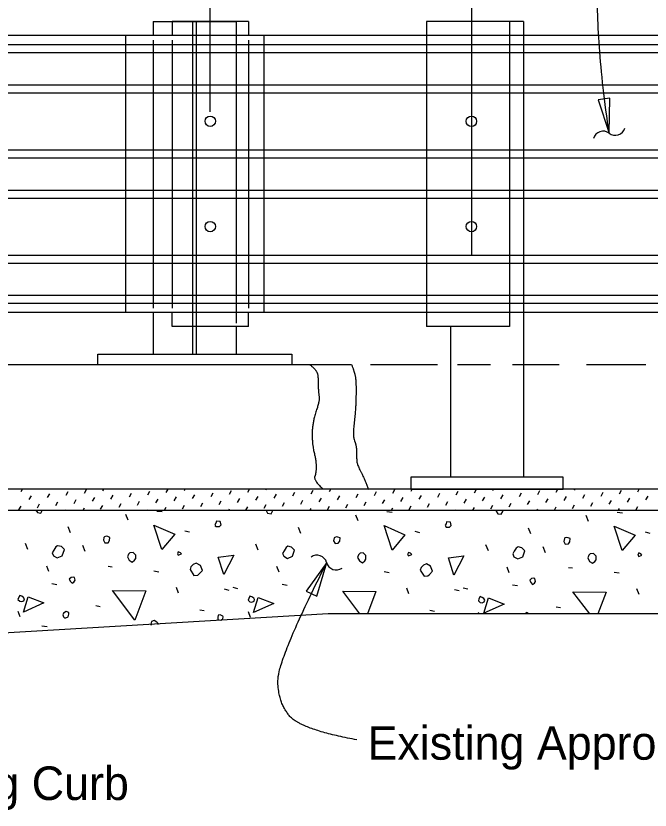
# Model space of a CAD drawing. Extents: x 21652.5 to 21723.2, y 56079.2 to 56117.9.
# Drawn here: x 21666.877 to 21670.692, y 56092.512 to 56097.288 of the extents above; entities that cross this region are included whole.
import ezdxf

# ---------------------------------------------------------------- set-up
doc = ezdxf.new("R2010")
doc.units = 0
for name, color, linetype in [('Dimension', 7, 'Continuous'), ('ExistSuperStruct', 7, 'Continuous'), ('Miscellaneous', 7, 'Continuous'), ('SteelMisc', 7, 'Continuous'), ('SteelMisc_h', 7, 'Continuous'), ('TextStructures', 7, 'Continuous')]:
    doc.layers.add(name, color=color, linetype=linetype)

msp = doc.modelspace()

# ---------------------------------------------------------------- linework, layer by layer
at = {"layer": 'Dimension'}
for points in [[(21670.4443, 56096.5821), (21670.4498, 56096.7932), (21670.3799, 56096.7832)], [(21668.7463, 56094.0005), (21668.6232, 56093.8288), (21668.6866, 56093.7979)]]:
    msp.add_lwpolyline(points, close=True, dxfattribs=at)
for centre, start, end in [((21670.4815, 56096.6294), 232.3142, 344.0414), ((21670.4086, 56096.535), 52.3142, 164.0414), ((21668.6877, 56093.9857), 14.5413, 126.2686), ((21668.8031, 56094.0157), 194.5413, 306.2686)]:
    msp.add_arc(centre, 0.0596, start, end, dxfattribs=at)
for points in [[(21670.4443, 56096.582), (21670.2321, 56098.0664), (21670.6716, 56098.0664)], [(21668.9275, 56092.9348), (21668.5908, 56092.9968), (21668.4527, 56093.1627), (21668.4527, 56093.4184), (21668.7461, 56094.0004)]]:
    msp.add_open_spline(points, degree=2, dxfattribs=at)
at = {"layer": 'ExistSuperStruct'}
for p, q in [((21663.535, 56095.1915), (21668.8956, 56095.1915)), ((21669.0102, 56095.1915), (21669.4133, 56095.1915)), ((21669.5335, 56095.1915), (21669.7306, 56095.1915)), ((21669.8642, 56095.1915), (21670.1448, 56095.1915)), ((21670.3084, 56095.1915), (21670.6659, 56095.1915)), ((21673.8983, 56094.4417), (21663.535, 56094.4417)), ((21663.535, 56094.3166), (21673.8983, 56094.3166)), ((21668.7549, 56093.6915), (21664.5351, 56093.4415)), ((21673.8983, 56093.6916), (21668.7549, 56093.6916))]:
    msp.add_line(p, q, dxfattribs=at)
for points in [[(21668.6455, 56095.1902), (21668.6889, 56095.1567), (21668.6956, 56095.0999), (21668.6956, 56095.0231), (21668.7056, 56094.9797), (21668.6589, 56094.8393), (21668.6589, 56094.709), (21668.6823, 56094.6155), (21668.6831, 56094.5403), (21668.6656, 56094.4952), (21668.7257, 56094.4418)], [(21668.8956, 56095.1915), (21668.9161, 56095.14), (21668.9227, 56095.0832), (21668.9227, 56095.0064), (21668.9207, 56094.9263), (21668.9023, 56094.7576), (21668.9248, 56094.7058), (21668.9265, 56094.6356), (21668.9265, 56094.5955), (21668.9758, 56094.4986), (21668.9983, 56094.4401)]]:
    msp.add_open_spline(points, degree=2, dxfattribs=at)
at = {"layer": 'Miscellaneous'}
for p, q in [((21668.046, 56096.7118), (21668.046, 56100.8638)), ((21669.6168, 56099.3652), (21669.6168, 56095.8462)), ((21668.2751, 56097.2541), (21667.8167, 56097.2541)), ((21667.8167, 56097.2541), (21667.8167, 56097.1708)), ((21668.2751, 56097.2541), (21668.2751, 56097.1708)), ((21669.8459, 56097.2539), (21669.3459, 56097.2539)), ((21669.3459, 56097.2539), (21669.3459, 56095.4208)), ((21669.8459, 56097.2539), (21669.8459, 56095.4208)), ((21667.5355, 56097.1708), (21667.5355, 56095.5041)), ((21667.8167, 56097.1422), (21667.8167, 56095.5303)), ((21668.2751, 56097.1422), (21668.2751, 56095.5303)), ((21668.3688, 56097.1708), (21668.3688, 56095.5041)), ((21667.5355, 56097.1151), (21673.905, 56097.1151)), ((21667.5355, 56097.0669), (21673.905, 56097.0669)), ((21667.5355, 56096.8741), (21673.905, 56096.8741)), ((21667.5355, 56096.8258), (21673.905, 56096.8258)), ((21667.5355, 56096.4819), (21673.905, 56096.4819)), ((21667.5355, 56096.4336), (21673.905, 56096.4336)), ((21667.5355, 56096.2408), (21673.905, 56096.2408)), ((21667.5355, 56096.1927), (21673.905, 56096.1927)), ((21667.5355, 56095.8487), (21673.905, 56095.8487)), ((21667.5355, 56095.8005), (21673.905, 56095.8005)), ((21667.5355, 56095.6077), (21673.905, 56095.6077)), ((21667.5355, 56095.5595), (21673.905, 56095.5595)), ((21667.8167, 56095.4208), (21667.8167, 56095.5041)), ((21668.2751, 56095.4208), (21668.2751, 56095.5041)), ((21668.2751, 56095.4208), (21667.8167, 56095.4208)), ((21669.8459, 56095.4208), (21669.3459, 56095.4208)), ((21666.9082, 56094.4285), (21666.9159, 56094.4417)), ((21667.0189, 56094.4414), (21667.019, 56094.4417)), ((21667.0677, 56094.3926), (21667.0807, 56094.415)), ((21667.1783, 56094.4056), (21667.1913, 56094.428)), ((21667.289, 56094.4185), (21667.3019, 56094.4409)), ((21667.3996, 56094.4315), (21667.4055, 56094.4417)), ((21667.4484, 56094.3827), (21667.4614, 56094.4051)), ((21667.5591, 56094.3956), (21667.572, 56094.418)), ((21667.6697, 56094.4086), (21667.6827, 56094.431)), ((21667.7803, 56094.4216), (21667.792, 56094.4417)), ((21667.891, 56094.4345), (21667.8951, 56094.4417)), ((21667.9398, 56094.3857), (21667.9528, 56094.4081)), ((21668.0504, 56094.3987), (21668.0634, 56094.421)), ((21668.1611, 56094.4116), (21668.174, 56094.434)), ((21668.2717, 56094.4246), (21668.2816, 56094.4417)), ((21668.3823, 56094.4375), (21668.3847, 56094.4417)), ((21668.4312, 56094.3887), (21668.4441, 56094.4111)), ((21668.5418, 56094.4017), (21668.5548, 56094.4241)), ((21668.6524, 56094.4146), (21668.6654, 56094.437)), ((21668.7631, 56094.4276), (21668.7712, 56094.4417)), ((21668.8737, 56094.4406), (21668.8743, 56094.4417)), ((21668.9225, 56094.3917), (21668.9355, 56094.4141)), ((21669.0332, 56094.4047), (21669.0461, 56094.4271)), ((21669.1438, 56094.4177), (21669.1568, 56094.44)), ((21669.2544, 56094.4306), (21669.2608, 56094.4417)), ((21669.3033, 56094.3818), (21669.3162, 56094.4042)), ((21669.4139, 56094.3947), (21669.4269, 56094.4171)), ((21669.5245, 56094.4077), (21669.5375, 56094.4301)), ((21669.6352, 56094.4207), (21669.6473, 56094.4417)), ((21669.7458, 56094.4336), (21669.7505, 56094.4417)), ((21669.7946, 56094.3848), (21669.8076, 56094.4072)), ((21669.9053, 56094.3978), (21669.9182, 56094.4202)), ((21670.0159, 56094.4107), (21670.0289, 56094.4331)), ((21670.1265, 56094.4237), (21670.1369, 56094.4417)), ((21670.2372, 56094.4367), (21670.2401, 56094.4417)), ((21670.286, 56094.3878), (21670.299, 56094.4102)), ((21670.3966, 56094.4008), (21670.4096, 56094.4232)), ((21670.5073, 56094.4137), (21670.5202, 56094.4361)), ((21670.6179, 56094.4267), (21670.6266, 56094.4417)), ((21666.9571, 56094.3796), (21666.97, 56094.402)), ((21667.1165, 56094.3438), (21667.1295, 56094.3662)), ((21667.2272, 56094.3567), (21667.2401, 56094.3791)), ((21667.3378, 56094.3697), (21667.3508, 56094.3921)), ((21667.4973, 56094.3338), (21667.5102, 56094.3562)), ((21667.6079, 56094.3468), (21667.6209, 56094.3692)), ((21667.7185, 56094.3598), (21667.7315, 56094.3822)), ((21667.8292, 56094.3727), (21667.8421, 56094.3951)), ((21667.9886, 56094.3369), (21668.0016, 56094.3592)), ((21668.0993, 56094.3498), (21668.1122, 56094.3722)), ((21668.2099, 56094.3628), (21668.2229, 56094.3852)), ((21668.3205, 56094.3757), (21668.3335, 56094.3981)), ((21668.48, 56094.3399), (21668.493, 56094.3623)), ((21668.5906, 56094.3528), (21668.6036, 56094.3752)), ((21668.7013, 56094.3658), (21668.7142, 56094.3882)), ((21668.8119, 56094.3788), (21668.8249, 56094.4012)), ((21668.9714, 56094.3429), (21668.9843, 56094.3653)), ((21669.082, 56094.3559), (21669.095, 56094.3782)), ((21669.1926, 56094.3688), (21669.2056, 56094.3912)), ((21669.3521, 56094.3329), (21669.3651, 56094.3553)), ((21669.4627, 56094.3459), (21669.4757, 56094.3683)), ((21669.5734, 56094.3589), (21669.5863, 56094.3813)), ((21669.684, 56094.3718), (21669.697, 56094.3942)), ((21669.8435, 56094.336), (21669.8564, 56094.3584)), ((21669.9541, 56094.3489), (21669.9671, 56094.3713)), ((21670.0647, 56094.3619), (21670.0777, 56094.3843)), ((21670.1754, 56094.3749), (21670.1883, 56094.3973)), ((21670.3348, 56094.339), (21670.3478, 56094.3614)), ((21670.4455, 56094.352), (21670.4584, 56094.3743)), ((21670.5561, 56094.3649), (21670.5691, 56094.3873)), ((21670.6667, 56094.3779), (21670.6797, 56094.4003)), ((21666.8953, 56094.3178), (21666.9082, 56094.3402)), ((21667.0059, 56094.3308), (21667.0189, 56094.3532)), ((21667.1779, 56094.3166), (21667.1783, 56094.3173)), ((21667.281, 56094.3166), (21667.289, 56094.3303)), ((21667.3866, 56094.3209), (21667.3996, 56094.3433)), ((21667.6675, 56094.3166), (21667.6697, 56094.3204)), ((21667.7239, 56094.3106), (21667.7557, 56094.3071)), ((21667.7707, 56094.3166), (21667.7803, 56094.3333)), ((21667.878, 56094.3239), (21667.891, 56094.3463)), ((21668.1572, 56094.3166), (21668.1611, 56094.3234)), ((21668.2603, 56094.3166), (21668.2717, 56094.3363)), ((21668.3694, 56094.3269), (21668.3823, 56094.3493)), ((21668.6468, 56094.3166), (21668.6524, 56094.3264)), ((21668.7501, 56094.317), (21668.7631, 56094.3394)), ((21668.8607, 56094.3299), (21668.8737, 56094.3523)), ((21669.1364, 56094.3166), (21669.1438, 56094.3294)), ((21669.2415, 56094.32), (21669.2544, 56094.3424)), ((21669.5229, 56094.3166), (21669.5245, 56094.3195)), ((21669.626, 56094.3166), (21669.6352, 56094.3324)), ((21669.7328, 56094.323), (21669.7458, 56094.3454)), ((21670.0125, 56094.3166), (21670.0159, 56094.3225)), ((21670.1156, 56094.3166), (21670.1265, 56094.3355)), ((21670.2242, 56094.326), (21670.2372, 56094.3484)), ((21670.5021, 56094.3166), (21670.5073, 56094.3255)), ((21670.6052, 56094.3166), (21670.6179, 56094.3385)), ((21667.5513, 56094.2547), (21667.5372, 56094.29)), ((21668.936, 56094.2511), (21668.9218, 56094.2865)), ((21669.1086, 56094.3071), (21669.1404, 56094.3036)), ((21670.3207, 56094.2476), (21670.3065, 56094.283)), ((21670.4933, 56094.3036), (21670.5251, 56094.3)), ((21667.2054, 56094.1798), (21667.1913, 56094.2152)), ((21667.8919, 56094.1922), (21667.9201, 56094.1851)), ((21668.5901, 56094.1763), (21668.576, 56094.2116)), ((21669.2765, 56094.1886), (21669.3048, 56094.1816)), ((21669.9748, 56094.1727), (21669.9607, 56094.2081)), ((21670.6612, 56094.1851), (21670.6895, 56094.178)), ((21666.9491, 56094.079), (21666.935, 56094.1144)), ((21667.2932, 56094.0673), (21667.2791, 56094.1027)), ((21668.3338, 56094.0755), (21668.3197, 56094.1109)), ((21669.7185, 56094.072), (21669.7043, 56094.1073)), ((21670.0626, 56094.0602), (21670.0484, 56094.0956)), ((21667.0746, 56093.9465), (21667.0623, 56093.98)), ((21667.4311, 56093.9789), (21667.4558, 56093.9754)), ((21668.4593, 56093.9429), (21668.4469, 56093.9765)), ((21669.844, 56093.9394), (21669.8316, 56093.973)), ((21667.7069, 56093.9506), (21667.7369, 56093.9453)), ((21669.0915, 56093.9471), (21669.1216, 56093.9418)), ((21670.2004, 56093.9718), (21670.2252, 56093.9683)), ((21670.4762, 56093.9436), (21670.5063, 56093.9382)), ((21667.0934, 56093.8746), (21667.1235, 56093.8693)), ((21667.8554, 56093.8163), (21667.843, 56093.8499)), ((21668.1294, 56093.8428), (21668.1576, 56093.8357)), ((21668.1818, 56093.8528), (21668.21, 56093.8457)), ((21668.4781, 56093.8711), (21668.5082, 56093.8658)), ((21669.24, 56093.8127), (21669.2277, 56093.8463)), ((21669.514, 56093.8393), (21669.5423, 56093.8322)), ((21669.5664, 56093.8492), (21669.5947, 56093.8422)), ((21669.8628, 56093.8675), (21669.8929, 56093.8622)), ((21670.6247, 56093.8092), (21670.6123, 56093.8428)), ((21667.3568, 56093.742), (21667.3834, 56093.7367)), ((21670.1262, 56093.735), (21670.1527, 56093.7297)), ((21666.9032, 56093.6737), (21666.8908, 56093.7073)), ((21667.9826, 56093.7173), (21668.0092, 56093.712)), ((21668.2878, 56093.6702), (21668.2755, 56093.7038)), ((21669.3673, 56093.7137), (21669.3938, 56093.7084)), ((21669.6633, 56093.6915), (21669.6601, 56093.7002)), ((21667.0333, 56093.6201), (21667.0652, 56093.6165))]:
    msp.add_line(p, q, dxfattribs=at)
for points in [[(21666.9975, 56094.3166), (21667.0057, 56094.3018), (21667.0269, 56094.2982), (21667.0357, 56094.3142), (21667.0363, 56094.3166)], [(21668.3803, 56094.3166), (21668.3815, 56094.3142)], [(21668.3815, 56094.3142), (21668.3904, 56094.2982), (21668.4116, 56094.2947), (21668.4204, 56094.3106), (21668.4219, 56094.3166)], [(21669.7632, 56094.3166), (21669.7662, 56094.3106)], [(21669.7662, 56094.3106), (21669.775, 56094.2947), (21669.7963, 56094.2912), (21669.8051, 56094.3071), (21669.8075, 56094.3166)], [(21667.7546, 56094.0797), (21667.7069, 56094.2264), (21667.8324, 56094.1716), (21667.7546, 56094.0797)], [(21668.0792, 56094.2169), (21668.1004, 56094.2169), (21668.1111, 56094.2275), (21668.1058, 56094.247), (21668.0828, 56094.2488), (21668.0792, 56094.2381), (21668.0739, 56094.2293), (21668.0792, 56094.2169), (21668.0757, 56094.2205)], [(21669.1393, 56094.0761), (21669.0915, 56094.2229), (21669.2171, 56094.1681), (21669.1393, 56094.0761)], [(21669.4639, 56094.2134), (21669.4851, 56094.2134), (21669.4957, 56094.224), (21669.4904, 56094.2434), (21669.4674, 56094.2452), (21669.4639, 56094.2346), (21669.4586, 56094.2258), (21669.4639, 56094.2134), (21669.4604, 56094.2169)], [(21670.5239, 56094.0726), (21670.4762, 56094.2193), (21670.6017, 56094.1645), (21670.5239, 56094.0726)], [(21667.4028, 56094.1345), (21667.4116, 56094.1186), (21667.4311, 56094.1203), (21667.4399, 56094.1327), (21667.4417, 56094.1521), (21667.4293, 56094.1575), (21667.4205, 56094.1592), (21667.4099, 56094.1557), (21667.4063, 56094.1521), (21667.4028, 56094.1345)], [(21668.7875, 56094.1309), (21668.7963, 56094.115), (21668.8158, 56094.1168), (21668.8246, 56094.1292), (21668.8264, 56094.1486), (21668.814, 56094.1539), (21668.8052, 56094.1557), (21668.7946, 56094.1521), (21668.791, 56094.1486), (21668.7875, 56094.1309)], [(21670.1722, 56094.1274), (21670.181, 56094.1115), (21670.2004, 56094.1133), (21670.2093, 56094.1256), (21670.2111, 56094.1451), (21670.1987, 56094.1504), (21670.1898, 56094.1521), (21670.1792, 56094.1486), (21670.1757, 56094.1451), (21670.1722, 56094.1274)], [(21667.1029, 56094.0419), (21667.1259, 56094.0295), (21667.1559, 56094.0419), (21667.1683, 56094.079), (21667.1506, 56094.0967), (21667.1277, 56094.102), (21667.1171, 56094.095), (21667.1047, 56094.0755), (21667.0958, 56094.0596), (21667.1029, 56094.0419)], [(21668.4876, 56094.0384), (21668.5106, 56094.026), (21668.5406, 56094.0384), (21668.553, 56094.0755), (21668.5353, 56094.0932), (21668.5123, 56094.0985), (21668.5017, 56094.0914), (21668.4894, 56094.072), (21668.4805, 56094.0561), (21668.4876, 56094.0384)], [(21669.8723, 56094.0349), (21669.8952, 56094.0225), (21669.9253, 56094.0349), (21669.9377, 56094.072), (21669.92, 56094.0897), (21669.897, 56094.095), (21669.8864, 56094.0879), (21669.874, 56094.0684), (21669.8652, 56094.0525), (21669.8723, 56094.0349)], [(21667.5478, 56094.0355), (21667.5584, 56094.0143), (21667.576, 56094.0037), (21667.5902, 56094.0143), (21667.5973, 56094.0249), (21667.5973, 56094.0461), (21667.5814, 56094.062), (21667.5619, 56094.0602), (21667.5531, 56094.0514), (21667.5478, 56094.0355)], [(21667.8536, 56094.0443), (21667.873, 56094.0532), (21667.866, 56094.0602), (21667.8536, 56094.0655), (21667.8483, 56094.0532), (21667.8536, 56094.0443)], [(21668.127, 56093.9288), (21668.0934, 56094.0331), (21668.1871, 56094.0455), (21668.127, 56093.9288)], [(21668.9324, 56094.0319), (21668.943, 56094.0107), (21668.9607, 56094.0001), (21668.9749, 56094.0107), (21668.9819, 56094.0213), (21668.9819, 56094.0425), (21668.966, 56094.0585), (21668.9466, 56094.0567), (21668.9377, 56094.0479), (21668.9324, 56094.0319)], [(21669.2383, 56094.0408), (21669.2577, 56094.0496), (21669.2506, 56094.0567), (21669.2383, 56094.062), (21669.233, 56094.0496), (21669.2383, 56094.0408)], [(21669.5116, 56093.9252), (21669.4781, 56094.0295), (21669.5717, 56094.0419), (21669.5116, 56093.9252)], [(21670.3171, 56094.0284), (21670.3277, 56094.0072), (21670.3454, 56093.9966), (21670.3595, 56094.0072), (21670.3666, 56094.0178), (21670.3666, 56094.039), (21670.3507, 56094.0549), (21670.3313, 56094.0532), (21670.3224, 56094.0443), (21670.3171, 56094.0284)], [(21670.6229, 56094.0372), (21670.6424, 56094.0461), (21670.6353, 56094.0532), (21670.6229, 56094.0585), (21670.6176, 56094.0461), (21670.6229, 56094.0372)], [(21667.9243, 56093.9595), (21667.9473, 56093.9223), (21667.9703, 56093.9241), (21667.9791, 56093.9329), (21667.9985, 56093.9524), (21667.9862, 56093.9824), (21667.9614, 56093.9966), (21667.9437, 56093.9895), (21667.9296, 56093.9754), (21667.9243, 56093.9595)], [(21669.309, 56093.9559), (21669.332, 56093.9188), (21669.3549, 56093.9206), (21669.3638, 56093.9294), (21669.3832, 56093.9489), (21669.3708, 56093.9789), (21669.3461, 56093.9931), (21669.3284, 56093.986), (21669.3143, 56093.9718), (21669.309, 56093.9559)], [(21667.2048, 56093.887), (21667.2154, 56093.8764), (21667.226, 56093.8834), (21667.2331, 56093.8941), (21667.2296, 56093.9117), (21667.2207, 56093.9135), (21667.2084, 56093.9117), (21667.1977, 56093.9011), (21667.2048, 56093.887)], [(21669.9742, 56093.8799), (21669.9848, 56093.8693), (21669.9954, 56093.8764), (21670.0025, 56093.887), (21669.9989, 56093.9047), (21669.9901, 56093.9064), (21669.9777, 56093.9047), (21669.9671, 56093.8941), (21669.9742, 56093.8799)], [(21667.592, 56093.6554), (21667.4576, 56093.8322), (21667.6574, 56093.8304), (21667.592, 56093.6554)], [(21666.8996, 56093.7679), (21666.912, 56093.7662), (21666.9244, 56093.7715), (21666.9279, 56093.7821), (21666.9226, 56093.7909), (21666.912, 56093.798), (21666.8996, 56093.8033), (21666.8925, 56093.7891), (21666.889, 56093.7785), (21666.8996, 56093.7679)], [(21666.922, 56093.7031), (21666.9503, 56093.7951), (21667.0439, 56093.7579), (21666.922, 56093.7031)], [(21668.2843, 56093.7644), (21668.2967, 56093.7626), (21668.309, 56093.7679), (21668.3126, 56093.7785), (21668.3073, 56093.7874), (21668.2967, 56093.7944), (21668.2843, 56093.7997), (21668.2772, 56093.7856), (21668.2737, 56093.775), (21668.2843, 56093.7644)], [(21668.3067, 56093.6996), (21668.3349, 56093.7915), (21668.4286, 56093.7544), (21668.3067, 56093.6996)], [(21668.9465, 56093.6915), (21668.8423, 56093.8286), (21669.042, 56093.8269), (21668.9915, 56093.6915)], [(21669.669, 56093.7608), (21669.6813, 56093.7591), (21669.6937, 56093.7644), (21669.6973, 56093.775), (21669.692, 56093.7838), (21669.6813, 56093.7909), (21669.669, 56093.7962), (21669.6619, 56093.7821), (21669.6584, 56093.7715), (21669.669, 56093.7608)], [(21669.6913, 56093.6961), (21669.7196, 56093.788), (21669.8133, 56093.7509), (21669.6913, 56093.6961)], [(21670.3285, 56093.6915), (21670.227, 56093.8251), (21670.4267, 56093.8233), (21670.3775, 56093.6915)], [(21667.1695, 56093.6678), (21667.1765, 56093.6678), (21667.1907, 56093.6749), (21667.196, 56093.6908), (21667.1942, 56093.6996), (21667.1801, 56093.7067), (21667.1624, 56093.6961), (21667.1589, 56093.6855), (21667.1624, 56093.6749), (21667.1695, 56093.6678)], [(21669.9638, 56093.6915), (21669.9636, 56093.6925), (21669.9494, 56093.6996), (21669.936, 56093.6915)], [(21667.7317, 56093.6276), (21667.7334, 56093.6342), (21667.7245, 56093.643), (21667.7086, 56093.6519), (21667.6927, 56093.6466), (21667.6874, 56093.6307), (21667.6902, 56093.625)], [(21668.0905, 56093.6589), (21668.1099, 56093.6536), (21668.1223, 56093.6625), (21668.1241, 56093.6749), (21668.1205, 56093.6784), (21668.1064, 56093.6855), (21668.094, 56093.6837), (21668.0922, 56093.6713), (21668.0905, 56093.6589)]]:
    msp.add_lwpolyline(points, dxfattribs=at)
at = {"layer": 'SteelMisc'}
for p, q in [((21667.7022, 56097.2541), (21668.2022, 56097.2541)), ((21667.7022, 56097.2541), (21667.7022, 56097.1708)), ((21667.5355, 56097.1707), (21657.2387, 56097.1707)), ((21657.2387, 56097.1152), (21667.5355, 56097.1152)), ((21657.2387, 56097.0669), (21667.5355, 56097.0669)), ((21657.2387, 56096.8741), (21667.5355, 56096.8741)), ((21657.2387, 56096.8259), (21667.5355, 56096.8259)), ((21657.2387, 56096.4819), (21667.5355, 56096.4819)), ((21657.2387, 56096.4337), (21667.5355, 56096.4337)), ((21657.2387, 56096.2409), (21667.5355, 56096.2409)), ((21657.2387, 56096.1928), (21667.5355, 56096.1928)), ((21657.2387, 56095.8488), (21667.5355, 56095.8488)), ((21657.2387, 56095.8006), (21667.5355, 56095.8006)), ((21657.2387, 56095.6078), (21667.5355, 56095.6078)), ((21657.2387, 56095.5595), (21667.5355, 56095.5595)), ((21667.5355, 56095.504), (21657.2387, 56095.504)), ((21667.7022, 56095.5041), (21667.7022, 56095.2541)), ((21668.2022, 56095.4208), (21668.2022, 56095.2541)), ((21667.3688, 56095.2541), (21668.5355, 56095.2541)), ((21667.3688, 56095.1916), (21667.3688, 56095.2541)), ((21667.7022, 56095.2541), (21668.2022, 56095.2541)), ((21668.5355, 56095.2541), (21668.5355, 56095.1916)), ((21667.3688, 56095.1916), (21668.5355, 56095.1916))]:
    msp.add_line(p, q, dxfattribs=at)
for centre in [(21668.0459, 56096.654), (21668.0459, 56096.0209)]:
    msp.add_circle(centre, 0.0312, dxfattribs=at)
at = {"layer": 'SteelMisc_h'}
for p, q in [((21667.9417, 56095.2541), (21667.9417, 56097.2541)), ((21667.9626, 56095.2541), (21667.9626, 56097.2541)), ((21668.2022, 56097.2541), (21668.2022, 56095.4411)), ((21669.9292, 56097.2539), (21669.8459, 56097.2539)), ((21669.9292, 56097.2539), (21669.9292, 56094.5146)), ((21673.905, 56097.1706), (21667.5355, 56097.1706)), ((21667.7022, 56097.1422), (21667.7022, 56095.5303)), ((21673.905, 56095.5039), (21667.5355, 56095.5039)), ((21669.4917, 56095.4208), (21669.4917, 56094.5146))]:
    msp.add_line(p, q, dxfattribs=at)
msp.add_lwpolyline([(21670.1688, 56094.4417), (21670.1688, 56094.5146), (21669.2521, 56094.5146), (21669.2521, 56094.4417)], close=True, dxfattribs=at)
for centre in [(21669.6167, 56096.6538), (21669.6167, 56096.0207)]:
    msp.add_circle(centre, 0.0312, dxfattribs=at)

# ---------------------------------------------------------------- texts
at = {"layer": 'TextStructures'}
for s, p in [('Existing Approach Slab', (21668.9916, 56092.8154)), ('Existing Curb', (21665.953, 56092.5731))]:
    msp.add_text(s, height=0.2016, dxfattribs=at).set_placement(p)

doc.saveas('drawing.dxf')
